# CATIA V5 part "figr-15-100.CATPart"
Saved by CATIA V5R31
Part number: Part1
Bounding box of the stored display mesh (mm): x -52.43 to 60.529, y -25.631 to 32.893, z 0 to 4
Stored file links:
  D:\PROJECTS\Project 2021\US EDITION\CATIA V5 6R 2021\Resources\Part Files\c15_catia_v5_6r2021_prt\figr-15-100.CATPart
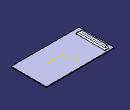
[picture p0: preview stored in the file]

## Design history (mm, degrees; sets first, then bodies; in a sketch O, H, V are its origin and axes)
SheetMetalParameters1: Thickness 1, BendRadius 5, KFactor 0.5 {= log(min(100,max(20*SheetMetalParameters1.BendRadius,SheetMetalParameters1.Thickness)/SheetMetalParameters1.Thickness))/log(100)/2}, ReliefRadialLength 1, ReliefAxialLength 2, MinimumBendRadius 0
Body1 (main body)
  Sketch1 on xy-plane, origin (0, 0, 0), H (1, 0, 0), V (0, 1, 0)
    line L1 (-52.4297, 32.8934) -> (60.5286, 32.8934)
    line L2 (60.5286, 32.8934) -> (60.5286, -25.6312)
    line L3 (60.5286, -25.6312) -> (-52.4297, -25.6312)
    line L4 (-52.4297, -25.6312) -> (-52.4297, 32.8934)
    horizontal: L1 H, L3 H
    vertical: L2 V, L4 V
  Wall1: Thickness 1, Profile Sketch1
  Sketch2 on face of Wall1, origin (0, 0, 1), H (1, 0, 0), V (0, 1, 0)
    line L1 (-47.3159, -16.5837) -> (-43.073, -16.5837)
    line L2 (-43.073, -16.5837) -> (-43.073, 26.788)
    line L3 (-43.073, 26.788) -> (-47.3159, 26.788)
    line L4 (-47.3159, 26.788) -> (-47.3159, -16.5837)
    horizontal: L1 H, L3 H
    vertical: L2 V, L4 V
  d_Stamp1: Stamp_FilletRadius 2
